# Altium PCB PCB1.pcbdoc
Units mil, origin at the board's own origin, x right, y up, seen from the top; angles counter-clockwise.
Board outline 2810 x 3710 mil, 2 copper layers (Top Layer, Bottom Layer), stack 62.2 mil thick; 16 components, 42 nets, 118 pads, 116 vias.
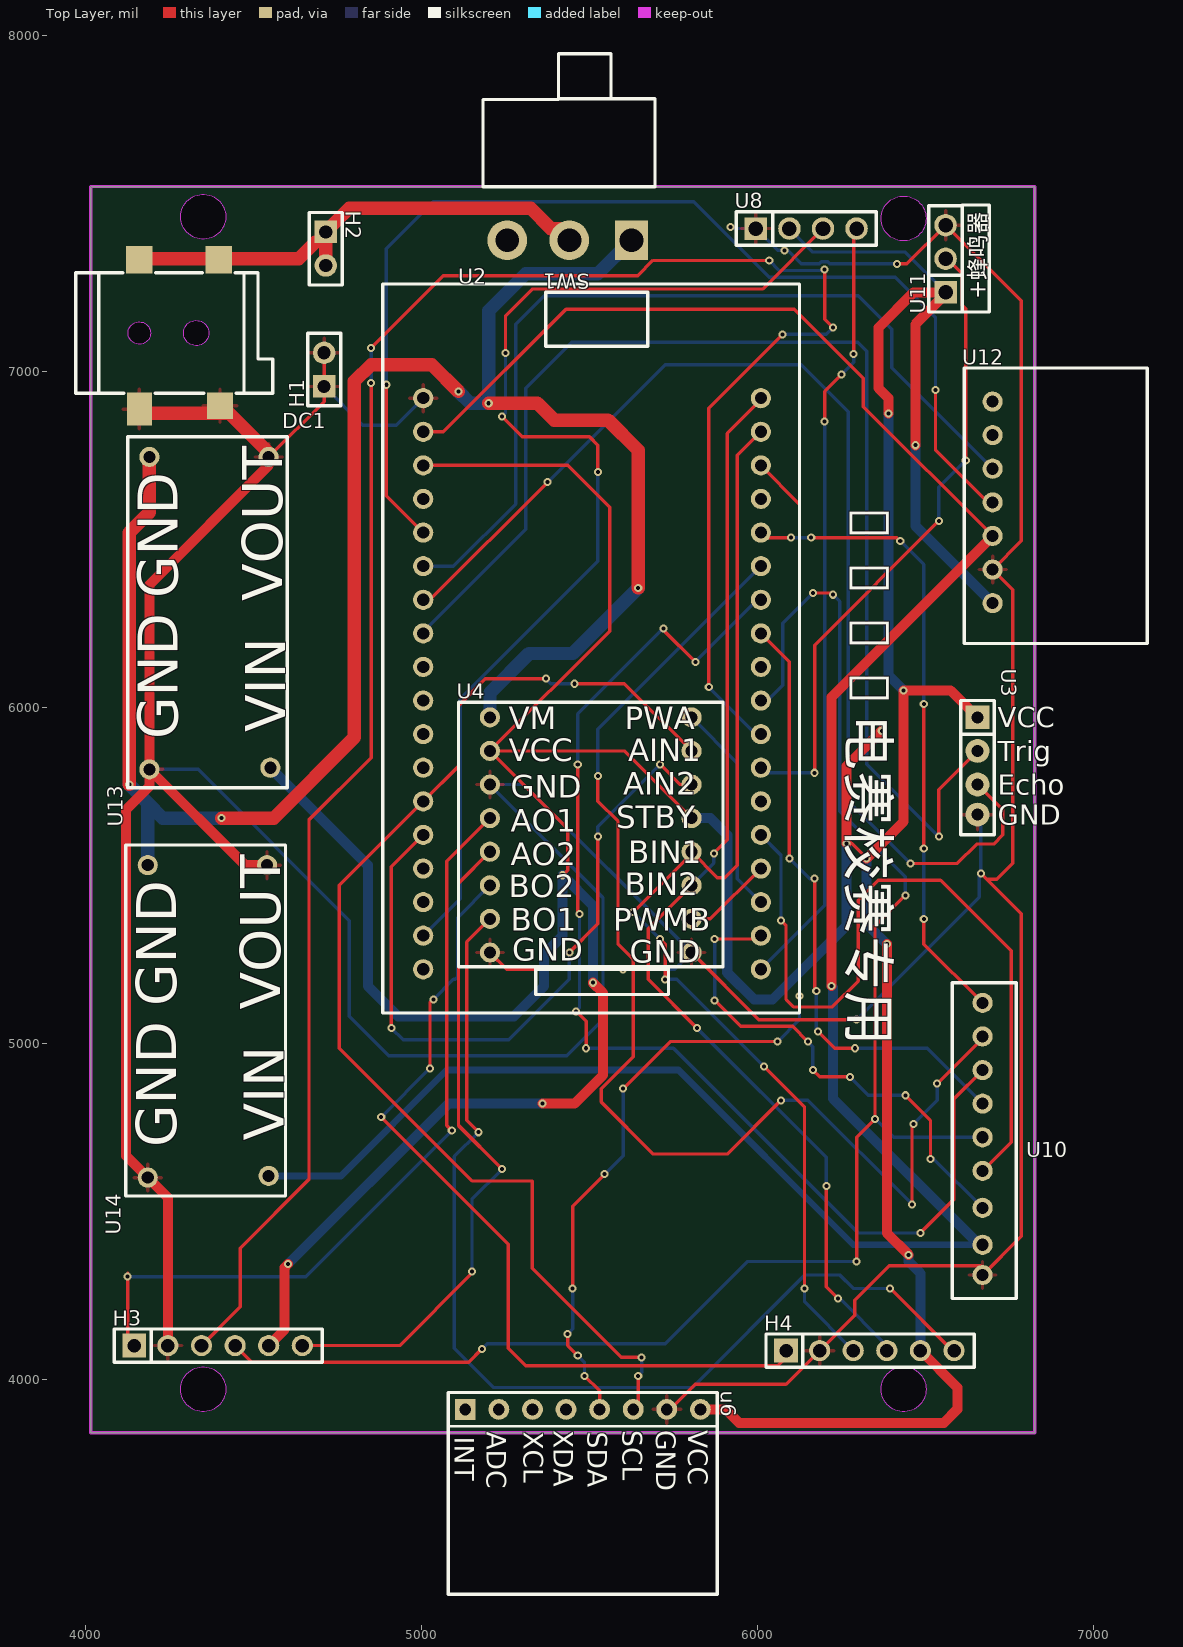
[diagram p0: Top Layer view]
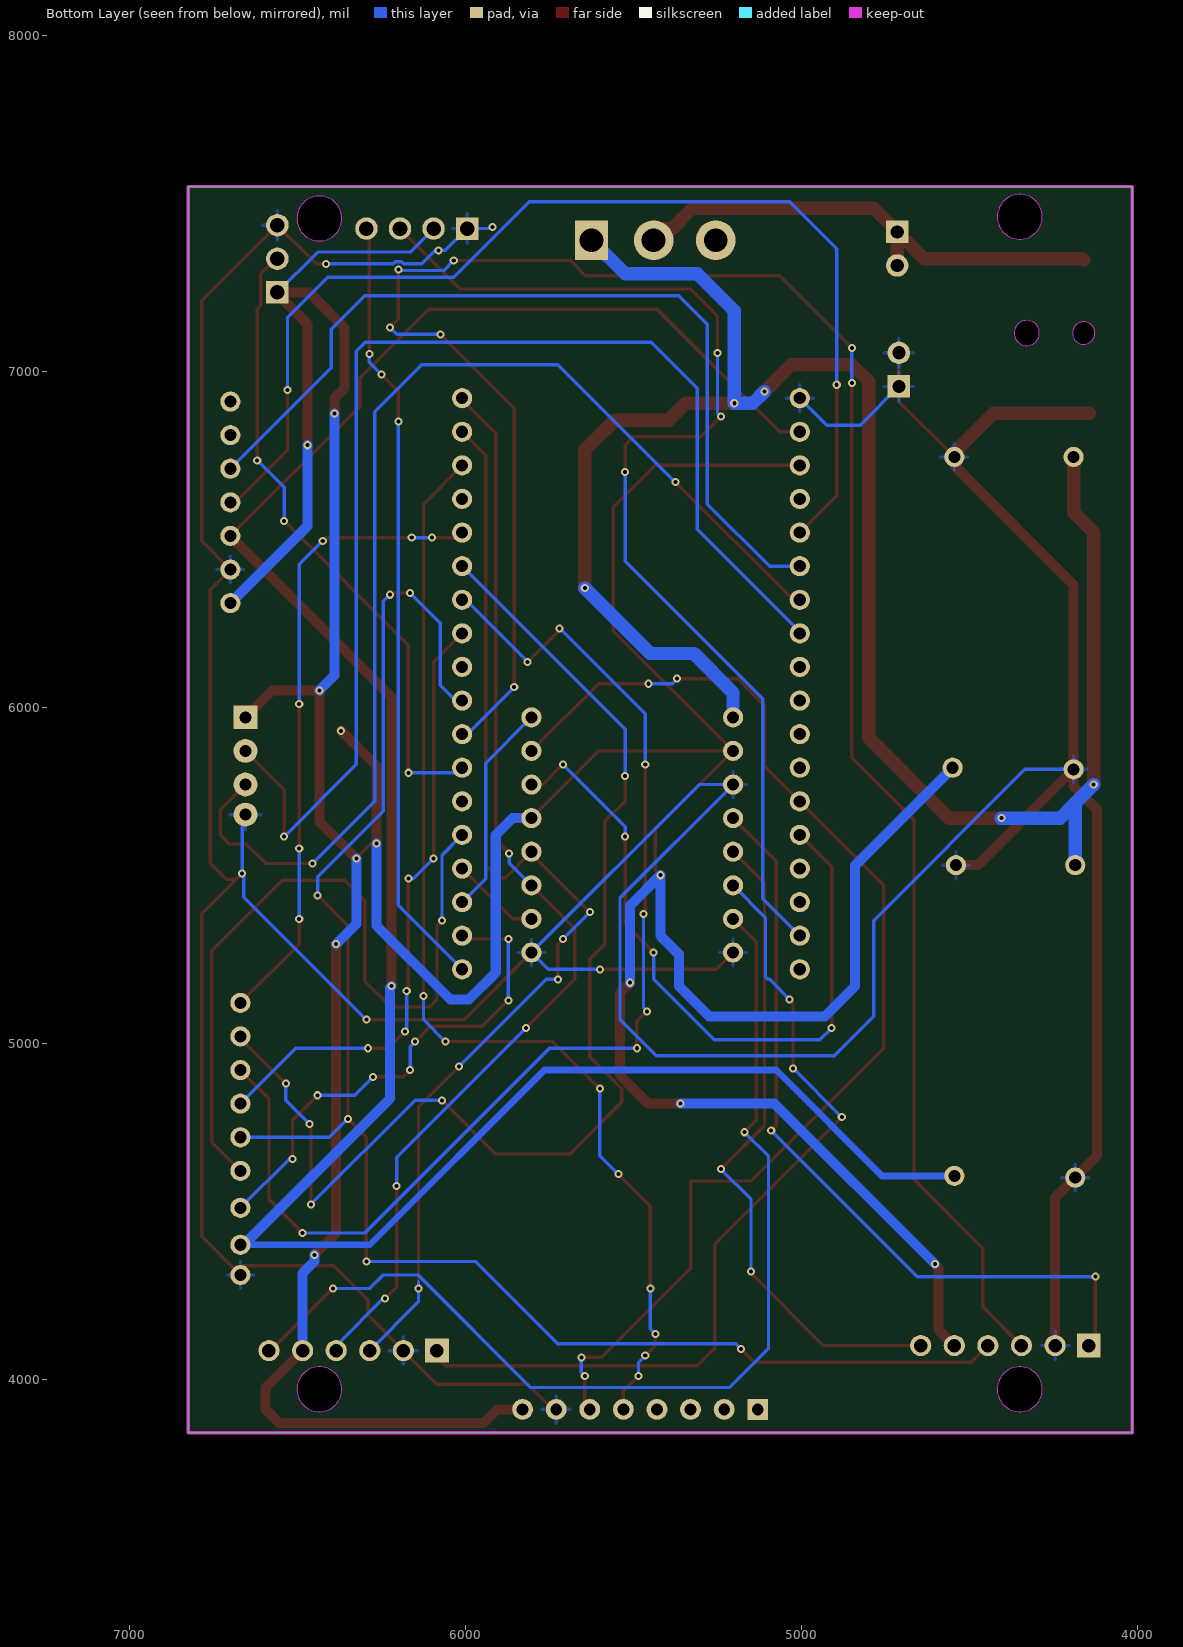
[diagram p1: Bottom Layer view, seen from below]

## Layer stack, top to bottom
Top Solder Mask Layer: solder mask 0.4, Dk 3.3
Top Layer: signal copper 1.4
Dielectric1: surface 59.4, FR4, Dk 4.5
Bottom Layer: signal copper 1.4
Bottom Solder Mask Layer: solder mask 0.4, Dk 3.3

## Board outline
4015,7550 4015,3840 6825,3840 6825,7550
cut-out: 4416.9,3970 4416.5,3962.8 4415.4,3955.6 4413.4,3948.6 4410.7,3941.9 4407.3,3935.5 4403.3,3929.5 4398.6,3924 4393.3,3919 4387.6,3914.6 4381.4,3910.9 4374.8,3907.8 4367.9,3905.5 4360.8,3904 4353.6,3903.2 4346.4,3903.2 4339.2,3904 4332.1,3905.5 4325.2,3907.8 4318.6,3910.9 4312.4,3914.6 4306.7,3919 4301.4,3924 4296.7,3929.5 4292.7,3935.5 4289.3,3941.9 4286.6,3948.6 4284.6,3955.6 4283.5,3962.8 4283.1,3970 4283.5,3977.2 4284.6,3984.4 4286.6,3991.4 4289.3,3998.1 4292.7,4004.5 4296.7,4010.5 4301.4,4016 4306.7,4021 4312.4,4025.4 4318.6,4029.1 4325.2,4032.2 4332.1,4034.5 4339.2,4036 4346.4,4036.8 4353.6,4036.8 4360.8,4036 4367.9,4034.5 4374.8,4032.2 4381.4,4029.1 4387.6,4025.4 4393.3,4021 4398.6,4016 4403.3,4010.5 4407.3,4004.5 4410.7,3998.1 4413.4,3991.4 4415.4,3984.4 4416.5,3977.2
cut-out: 6501.9,3970 6501.5,3962.8 6500.4,3955.6 6498.4,3948.6 6495.7,3941.9 6492.3,3935.5 6488.3,3929.5 6483.6,3924 6478.3,3919 6472.6,3914.6 6466.4,3910.9 6459.8,3907.8 6452.9,3905.5 6445.8,3904 6438.6,3903.2 6431.4,3903.2 6424.2,3904 6417.1,3905.5 6410.2,3907.8 6403.6,3910.9 6397.4,3914.6 6391.7,3919 6386.4,3924 6381.7,3929.5 6377.7,3935.5 6374.3,3941.9 6371.6,3948.6 6369.6,3955.6 6368.5,3962.8 6368.1,3970 6368.5,3977.2 6369.6,3984.4 6371.6,3991.4 6374.3,3998.1 6377.7,4004.5 6381.7,4010.5 6386.4,4016 6391.7,4021 6397.4,4025.4 6403.6,4029.1 6410.2,4032.2 6417.1,4034.5 6424.2,4036 6431.4,4036.8 6438.6,4036.8 6445.8,4036 6452.9,4034.5 6459.8,4032.2 6466.4,4029.1 6472.6,4025.4 6478.3,4021 6483.6,4016 6488.3,4010.5 6492.3,4004.5 6495.7,3998.1 6498.4,3991.4 6500.4,3984.4 6501.5,3977.2
cut-out: 4416.9,7460 4416.5,7452.8 4415.4,7445.6 4413.4,7438.6 4410.7,7431.9 4407.3,7425.5 4403.3,7419.5 4398.6,7414 4393.3,7409 4387.6,7404.6 4381.4,7400.9 4374.8,7397.8 4367.9,7395.5 4360.8,7394 4353.6,7393.2 4346.4,7393.2 4339.2,7394 4332.1,7395.5 4325.2,7397.8 4318.6,7400.9 4312.4,7404.6 4306.7,7409 4301.4,7414 4296.7,7419.5 4292.7,7425.5 4289.3,7431.9 4286.6,7438.6 4284.6,7445.6 4283.5,7452.8 4283.1,7460 4283.5,7467.2 4284.6,7474.4 4286.6,7481.4 4289.3,7488.1 4292.7,7494.5 4296.7,7500.5 4301.4,7506 4306.7,7511 4312.4,7515.4 4318.6,7519.1 4325.2,7522.2 4332.1,7524.5 4339.2,7526 4346.4,7526.8 4353.6,7526.8 4360.8,7526 4367.9,7524.5 4374.8,7522.2 4381.4,7519.1 4387.6,7515.4 4393.3,7511 4398.6,7506 4403.3,7500.5 4407.3,7494.5 4410.7,7488.1 4413.4,7481.4 4415.4,7474.4 4416.5,7467.2
cut-out: 6501.9,7455 6501.5,7447.8 6500.4,7440.6 6498.4,7433.6 6495.7,7426.9 6492.3,7420.5 6488.3,7414.5 6483.6,7409 6478.3,7404 6472.6,7399.6 6466.4,7395.9 6459.8,7392.8 6452.9,7390.5 6445.8,7389 6438.6,7388.2 6431.4,7388.2 6424.2,7389 6417.1,7390.5 6410.2,7392.8 6403.6,7395.9 6397.4,7399.6 6391.7,7404 6386.4,7409 6381.7,7414.5 6377.7,7420.5 6374.3,7426.9 6371.6,7433.6 6369.6,7440.6 6368.5,7447.8 6368.1,7455 6368.5,7462.2 6369.6,7469.4 6371.6,7476.4 6374.3,7483.1 6377.7,7489.5 6381.7,7495.5 6386.4,7501 6391.7,7506 6397.4,7510.4 6403.6,7514.1 6410.2,7517.2 6417.1,7519.5 6424.2,7521 6431.4,7521.8 6438.6,7521.8 6445.8,7521 6452.9,7519.5 6459.8,7517.2 6466.4,7514.1 6472.6,7510.4 6478.3,7506 6483.6,7501 6488.3,7495.5 6492.3,7489.5 6495.7,7483.1 6498.4,7476.4 6500.4,7469.4 6501.5,7462.2

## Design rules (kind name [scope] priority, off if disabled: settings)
BoardOutlineClearance copperThickness1oz [All] p0: genericclearance=10 ignorepadtopadclearanceinfootprint=FALSE except(0: Arc-SplitContinuation Track-SplitContinuation SMDPad-SplitContinuation THPad-SplitContinuation Via-SplitContinuation Fill-SplitContinuation Poly-SplitContinuation Region-SplitContinuation Text-SplitContinuation)
BoardOutlineClearance copperThickness2oz [All] p0: genericclearance=10 ignorepadtopadclearanceinfootprint=FALSE except(0: Arc-SplitContinuation Track-SplitContinuation SMDPad-SplitContinuation THPad-SplitContinuation Via-SplitContinuation Fill-SplitContinuation Poly-SplitContinuation Region-SplitContinuation Text-SplitContinuation)
BoardOutlineClearance Plane_innerPlane [All] p0: genericclearance=10 ignorepadtopadclearanceinfootprint=FALSE except(0: Arc-SplitContinuation Track-SplitContinuation SMDPad-SplitContinuation THPad-SplitContinuation Via-SplitContinuation Fill-SplitContinuation Poly-SplitContinuation Region-SplitContinuation Text-SplitContinuation)
BoardOutlineClearance Copper_copperRegion [All] p0: genericclearance=10 ignorepadtopadclearanceinfootprint=FALSE except(0: Arc-SplitContinuation Track-SplitContinuation SMDPad-SplitContinuation THPad-SplitContinuation Via-SplitContinuation Fill-SplitContinuation Poly-SplitContinuation Region-SplitContinuation Text-SplitContinuation)
BoardOutlineClearance otherClearance [All] p0: genericclearance=10 ignorepadtopadclearanceinfootprint=FALSE except(0: Arc-SplitContinuation Track-SplitContinuation SMDPad-SplitContinuation THPad-SplitContinuation Via-SplitContinuation Fill-SplitContinuation Poly-SplitContinuation Region-SplitContinuation Text-SplitContinuation)
Clearance copperThickness1oz [All] p1: gap=7 ignorepadtopadclearanceinfootprint=FALSE
Clearance copperThickness2oz [All] p1: gap=7 ignorepadtopadclearanceinfootprint=FALSE
Clearance Plane_innerPlane [All] p1: gap=7 ignorepadtopadclearanceinfootprint=FALSE
Clearance Copper_copperRegion [All] p1: gap=7 ignorepadtopadclearanceinfootprint=FALSE
Clearance otherClearance [All] p1: gap=7 ignorepadtopadclearanceinfootprint=FALSE
DiffPairsRouting differentialPair [All] p1: maxuncoupledlength=10 minlimit=6 maxlimit=Infinity mostfreqgap=6 toplayer_minwidth=5 toplayer_prefwidth=10 toplayer_maxwidth=100 bottomlayer_minwidth=5 bottomlayer_prefwidth=10 bottomlayer_maxwidth=100
PasteMaskExpansion pasteMaskExpansion [All] p1: expansion=0
PlaneConnect innerPlane [All] p1: planeconnectstyle=Relief reliefexpansion=20 reliefentries=4 reliefconductorwidth=10 reliefairgap=10
PolygonConnect copperRegion [All] p1: connectstyle=Relief reliefentries=4 reliefconductorwidth=10 polygonreliefangle="90 Angle" airgapwidth=10
RoutingVias viaSize [All] p1: viastyle="Through Hole" holewidth=12.0078 minholewidth=11.811 maxholewidth=248.0314 width=12.0078 minwidth=11.811 maxwidth=248.0314
SolderMaskExpansion solderMaskExpansion [IsVia] p1: useseparateexpansions=TRUE expansion=-1000 expansionbottom=-1000
SolderMaskExpansion solderMaskExpansion [All] p2: useseparateexpansions=TRUE expansion=2 expansionbottom=2
Width copperThickness1oz [All] p1: maxlimit=100 minlimit=5 preferedwidth=10
Width copperThickness2oz [All] p1: maxlimit=100 minlimit=8 preferedwidth=10

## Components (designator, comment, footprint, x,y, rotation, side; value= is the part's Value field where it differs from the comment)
DC1 "DC050-T" DC-IN_DC050-T 4280,7110 r0 top
H1 "" HDR-TH_2P-P2.54-V-F 4710,7005 r90 top
H2 "" HDR-TH_2P-P2.54-V-F 4715,7365 r270 top
H3 "" HDR-TH_6P-P2.54-V-F 4395,4100 r0 top
H4 "" HDR-TH_6P-P2.54-V-F 6335,4085 r0 top
SW1 "SS-12D06L5" SW-TH_3P-P4.70_L11.1-W12.7 5440,7390 r180 top
U2 "" 5307 5265,7150 r0 top
U3 "HC-SR04" HC-SR04 6655,5820 r270 top
U4 "" TB6612 5110,6015 r0 top
u6 "mpu6050" MPU6050模块 5480,3960 r270 top
U8 "OLED-4P" HDR-TH_4P-P2.54-V-F 6145,7425 r0 top
U10 "" huidu 6650,4630 r0 top
U11 "蜂鸣器" 蜂鸣器 6560,7335 r90 top
U12 "" tcs34725 6885,6540 r0 top
U13 "" MP2236 4130,5750 r90 top
U14 "" MP2236 4125,4535 r90 top

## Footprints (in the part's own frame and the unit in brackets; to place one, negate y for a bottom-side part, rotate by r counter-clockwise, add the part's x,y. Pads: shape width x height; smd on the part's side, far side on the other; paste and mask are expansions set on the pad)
5307 [mil]
  round 60 hole 36: 1(745,-230) 2(745,-330) 3(745,-430) 4(745,-530) 5(745,-630) 6(745,-730) 7(745,-830) 8(745,-930) 9(745,-1030) 10(745,-1130) 11(745,-1230) 12(745,-1330) 13(745,-1430) 14(745,-1530) 15(745,-1630) 16(745,-1730) 17(745,-1830) 18(745,-1930) 19(-260,-1930) 20(-260,-1830) 21(-260,-1730) 22(-260,-1630) 23(-260,-1530) 24(-260,-1430) 25(-260,-1330) 26(-260,-1230) 27(-260,-1130) 28(-260,-1030) 29(-260,-930) 30(-260,-830) 31(-260,-730) 32(-260,-630) 33(-260,-530) 34(-260,-430) 35(-260,-330) 36(-260,-230)
  silkscreen extent -380,-2060 860,110
DC-IN_DC050-T [mil]
  rect 78.7x82.7 smd paste+0 mask+2: 1(-120.1,222.4) 1(116.1,222.4)
  rect 74.8x98.4 smd paste+0 mask+2: 2(-120.1,-222.4)
  rect 78.7x78.7 smd paste+0 mask+2: 3(120.1,-212.6)
  Board Outline Layer lines w0.1: -153.4,1.4 -152.7,-3.7 -151.1,-8.6 -148.8,-13.2 -145.9,-17.4 -142.3,-21 -138.3,-24.2 -133.8,-26.6 -128.9,-28.3 -123.9,-29.3 -118.8,-29.5 -113.7,-28.9 -108.8,-27.6 -104.1,-25.5 -99.8,-22.7 -96,-19.3 -92.7,-15.3 -90.1,-10.9 -88.2,-6.2 -87,-1.2 -86.6,3.9 -87,9 -88.2,14 -90.1,18.8 -92.7,23.2 -96,27.1 -99.8,30.6 -104.1,33.3 -108.8,35.4 -113.7,36.8 -118.8,37.4 -123.9,37.2 -128.9,36.2 -133.8,34.5 -138.3,32 -142.3,28.9 -145.9,25.2 -148.8,21 -151.1,16.4 -152.7,11.6 -153.4,6.5 -153.4,1.4 ; 11.9,1.2 12.7,-4.2 14.3,-9.4 16.6,-14.4 19.6,-18.9 23.3,-23 27.4,-26.5 32.1,-29.3 37.1,-31.5 42.4,-32.8 47.8,-33.4 53.3,-33.2 58.7,-32.2 63.8,-30.5 68.7,-28 73.1,-24.8 77.1,-21 80.4,-16.7 83.1,-11.9 85,-6.8 86.2,-1.5 86.6,3.9 86.2,9.4 85,14.7 83.1,19.8 80.4,24.6 77.1,28.9 73.1,32.7 68.7,35.9 63.8,38.4 58.7,40.1 53.3,41.1 47.8,41.3 42.4,40.7 37.1,39.3 32.1,37.2 27.4,34.4 23.3,30.9 19.6,26.8 16.6,22.2 14.3,17.3 12.7,12.1 11.9,6.7 11.9,1.2
  Board Outline Layer region: -86.6,3.9 -87,-1.2 -88.2,-6.2 -90.1,-10.9 -92.7,-15.3 -96,-19.3 -99.8,-22.7 -104.1,-25.5 -108.8,-27.6 -113.7,-28.9 -118.8,-29.5 -123.9,-29.3 -128.9,-28.3 -133.8,-26.6 -138.3,-24.2 -142.3,-21 -145.9,-17.4 -148.8,-13.2 -151.1,-8.6 -152.7,-3.7 -153.4,1.4 -153.4,6.5 -152.7,11.6 -151.1,16.4 -148.8,21 -145.9,25.2 -142.3,28.9 -138.3,32 -133.8,34.5 -128.9,36.2 -123.9,37.2 -118.8,37.4 -113.7,36.8 -108.8,35.4 -104.1,33.3 -99.8,30.6 -96,27.1 -92.7,23.2 -90.1,18.8 -88.2,14 -87,9
  Board Outline Layer region: -86.6,3.9 -87,-1.2 -88.2,-6.2 -90.1,-10.9 -92.7,-15.3 -96,-19.3 -99.8,-22.7 -104.1,-25.5 -108.8,-27.6 -113.7,-28.9 -118.8,-29.5 -123.9,-29.3 -128.9,-28.3 -133.8,-26.6 -138.3,-24.2 -142.3,-21 -145.9,-17.4 -148.8,-13.2 -151.1,-8.6 -152.7,-3.7 -153.4,1.4 -153.4,6.5 -152.7,11.6 -151.1,16.4 -148.8,21 -145.9,25.2 -142.3,28.9 -138.3,32 -133.8,34.5 -128.9,36.2 -123.9,37.2 -118.8,37.4 -113.7,36.8 -108.8,35.4 -104.1,33.3 -99.8,30.6 -96,27.1 -92.7,23.2 -90.1,18.8 -88.2,14 -87,9
  Board Outline Layer region: 86.6,3.9 86.2,-1.5 85,-6.8 83.1,-11.9 80.4,-16.7 77.1,-21 73.1,-24.8 68.7,-28 63.8,-30.5 58.7,-32.2 53.3,-33.2 47.8,-33.4 42.4,-32.8 37.1,-31.5 32.1,-29.3 27.4,-26.5 23.3,-23 19.6,-18.9 16.6,-14.4 14.3,-9.4 12.7,-4.2 11.9,1.2 11.9,6.7 12.7,12.1 14.3,17.3 16.6,22.2 19.6,26.8 23.3,30.9 27.4,34.4 32.1,37.2 37.1,39.3 42.4,40.7 47.8,41.3 53.3,41.1 58.7,40.1 63.8,38.4 68.7,35.9 73.1,32.7 77.1,28.9 80.4,24.6 83.1,19.8 85,14.7 86.2,9.4
  Board Outline Layer region: 86.6,3.9 86.2,-1.5 85,-6.8 83.1,-11.9 80.4,-16.7 77.1,-21 73.1,-24.8 68.7,-28 63.8,-30.5 58.7,-32.2 53.3,-33.2 47.8,-33.4 42.4,-32.8 37.1,-31.5 32.1,-29.3 27.4,-26.5 23.3,-23 19.6,-18.9 16.6,-14.4 14.3,-9.4 12.7,-4.2 11.9,1.2 11.9,6.7 12.7,12.1 14.3,17.3 16.6,22.2 19.6,26.8 23.3,30.9 27.4,34.4 32.1,37.2 37.1,39.3 42.4,40.7 47.8,41.3 53.3,41.1 58.7,40.1 63.8,38.4 68.7,35.9 73.1,32.7 77.1,28.9 80.4,24.6 83.1,19.8 85,14.7 86.2,9.4
  Multi-Layer board cut-out: -86.6,3.9 -87,-1.2 -88.2,-6.2 -90.1,-10.9 -92.7,-15.3 -96,-19.3 -99.8,-22.7 -104.1,-25.5 -108.8,-27.6 -113.7,-28.9 -118.8,-29.5 -123.9,-29.3 -128.9,-28.3 -133.8,-26.6 -138.3,-24.2 -142.3,-21 -145.9,-17.4 -148.8,-13.2 -151.1,-8.6 -152.7,-3.7 -153.4,1.4 -153.4,6.5 -152.7,11.6 -151.1,16.4 -148.8,21 -145.9,25.2 -142.3,28.9 -138.3,32 -133.8,34.5 -128.9,36.2 -123.9,37.2 -118.8,37.4 -113.7,36.8 -108.8,35.4 -104.1,33.3 -99.8,30.6 -96,27.1 -92.7,23.2 -90.1,18.8 -88.2,14 -87,9
  Multi-Layer board cut-out: 86.6,3.9 86.2,-1.5 85,-6.8 83.1,-11.9 80.4,-16.7 77.1,-21 73.1,-24.8 68.7,-28 63.8,-30.5 58.7,-32.2 53.3,-33.2 47.8,-33.4 42.4,-32.8 37.1,-31.5 32.1,-29.3 27.4,-26.5 23.3,-23 19.6,-18.9 16.6,-14.4 14.3,-9.4 12.7,-4.2 11.9,1.2 11.9,6.7 12.7,12.1 14.3,17.3 16.6,22.2 19.6,26.8 23.3,30.9 27.4,34.4 32.1,37.2 37.1,39.3 42.4,40.7 47.8,41.3 53.3,41.1 58.7,40.1 63.8,38.4 68.7,35.9 73.1,32.7 77.1,28.9 80.4,24.6 83.1,19.8 85,14.7 86.2,9.4
  silkscreen extent -309,-175 278,183
HC-SR04 [mil]
  rect 70.9x70.9 hole 36: 1(-150,0)
  round 70.9 hole 36: 2(-50,0) 3(50,0) 4(139.5,0)
  silkscreen extent -200,-50 200,50
HDR-TH_2P-P2.54-V-F [mil]
  rect 66.9x66.9 hole 39.4: 1(-50,0)
  round 66.9 hole 39.4: 2(50,0)
  silkscreen extent -108,-49 108,49
HDR-TH_4P-P2.54-V-F [mil]
  rect 66.9x66.9 hole 43.3: 1(-150,0)
  round 66.9 hole 43.3: 2(-50,0) 3(50,0) 4(150,0)
  silkscreen extent -208,-50 208,50
HDR-TH_6P-P2.54-V-F [mil]
  rect 70.9x70.9 hole 40.2: 1(-250,0)
  round 63 hole 40.2: 2(-150,0) 3(-50,0) 4(50,0) 5(150,0) 6(250,0)
  silkscreen extent -310,-49 310,49
huidu [mil]
  round 60 hole 36: 1(20,490) 2(20,390) 3(20,290) 4(20,190) 5(20,90) 6(20,-10) 7(20,-120) 8(20,-230) 9(20,-320)
  silkscreen extent -70,-390 120,550
MP2236 [mil]
  round 60 hole 36: 1(65,-60) 2(995,-60) 3(995,-415) 4(70,-420)
  silkscreen extent 10,-470 1055,5
MPU6050模块 [mil]
  round 62 hole 35: ADC(50,-249.9) GND(50,250.1) SCL(50,150.1) SDA(50,50.1) VCC(50,350.1) XCL(50,-149.9) XDA(50,-49.9)
  rect 62x62 hole 35: INT(50,-349.9)
  silkscreen extent 0,-400 600,400
SW-TH_3P-P4.70_L11.1-W12.7 [mil]
  rect 98.4x118.1 hole 70.9: 1(-185,0)
  round 118.1 hole 70.9: 2(0,0) 3(185,0)
  silkscreen extent -255,-555 257,-159
TB6612 [mil]
  round 60 hole 36: 1(93.7,-45) 2(93.7,-145) 3(93.7,-245) 4(93.7,-345) 5(93.7,-445) 6(93.7,-545) 7(93.7,-645) 8(93.7,-745) 9(693.7,-745) 10(693.7,-645) 11(693.7,-545) 12(693.7,-445) 13(693.7,-345) 14(693.7,-245) 15(693.7,-145) 16(693.7,-45)
  silkscreen extent 0,-787 787,0
tcs34725 [mil]
  round 60 hole 36: 1(-185,370) 2(-185,270) 3(-185,170) 4(-185,70) 5(-185,-30) 6(-185,-130) 7(-185,-230)
  silkscreen extent -270,-350 275,470
蜂鸣器 [mil]
  rect 66.9x66.9 hole 43.3 paste+0 mask+2: 1(-100,0)
  round 66.9 hole 43.3 paste+0 mask+2: 2(0,0) 3(100,0)
  silkscreen extent -158,-130 160,50

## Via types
v1: diameter 24, hole 12, Top Layer to Bottom Layer, 116 vias

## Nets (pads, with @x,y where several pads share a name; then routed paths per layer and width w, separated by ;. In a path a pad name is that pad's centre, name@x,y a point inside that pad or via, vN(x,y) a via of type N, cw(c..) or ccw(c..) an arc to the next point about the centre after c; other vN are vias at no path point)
+3.3V: U2.35 U10.8 U12.5 U14.4 | length 7137.5
  Top Layer w10: U2.35 5065,6820 5430,7185 6110,7185 6315,6980 6315,6895 U12.5
  Top Layer w30: v1(6220,5170) 6220,6030 U12.5
  Bottom Layer w20: U14.4 4760,4605 5075,4920 5765,4920 6285,4400 U10.8@6660,4400
  Bottom Layer w30: v1(6220,5170) 6225,5165 6225,4835 6660,4400 U10.8
+5V: H3.5 H4.5 U2.34 U3.1 U4.2 U4.13 u6.VCC U8.2 U11.1 U12.7 U13.4 | length 14469.1
  Top Layer w10: U2.34 5435,6720 5560,6595 5560,6226.3 U4.2 ; v1(5420,5500) 5435,5515 5435,5638.7 U4.2 ; U4.13 5603.7,5870 U4.2 ; v1(6265,5595) 6280,5595 v1(6325,5550)
  Top Layer w30: H3.5 4592.5,4147.5 4592.5,4332.5 v1(4602.5,4342.5) ; v1(5360,4820.1) 5455.1,4820.1 5540,4905 5540,5150 v1(5510,5180) ; u6.VCC 5905,3910 5945,3870 6555,3870 6595,3910 6595,3975 H4.5 ; v1(6265,5595) 6265,5825 v1(6370,5930) ; v1(6325,5550) 6435,5660 v1(6435,6050) 6575,6050 U3.1 ; v1(6385,5295) 6385,4435 v1(6450,4370) ; v1(6390,6875) 6390,6920 6360,6950 6360,7130 6465,7235 6565,7235 6470,7140 v1(6470,6780)
  Bottom Layer w10: U8.2 6165,7355 6440,7355 U11.1
  Bottom Layer w30: U13.4 4840,5530 4840,5170 4930,5080 5275,5080 5365,5170 5365,5265 5420,5320 v1(5420,5500) 5510,5410 v1(5510,5180) ; v1(4602.5,4342.5) 5080.1,4820.1 v1(5360,4820.1) ; U4.13 5860,5670 5910,5620 5910,5210 5990,5130 6045,5130 6265,5350 v1(6265,5595) ; v1(6325,5550) 6325,5355 v1(6385,5295) ; v1(6390,6875) 6390,6095 v1(6435,6050) ; v1@6450,4371 6450,4350 6485,4315 H4.5 ; v1(6470,6780) 6470,6540 U12.7
+12V: SW1.1 U4.1 U13.2 U14.2 | length 5903
  Top Layer w40: v1(4130,5770) 4130,6520 4190,6580 U13.2 ; v1(4405,5670) 4560,5670 4800,5910 4800,6970 4850,7020 5030,7020 v1(5110,6940) ; v1(5200,6905) 5345,6905 5395,6855 5555,6855 5645,6765 v1(5645,6355)
  Bottom Layer w10: SW1.1 SW1.1@5625,7425
  Bottom Layer w40: v1(4130,5770) 4185,5715 ; U14.2 4185,5715 ; v1(4405,5670) 4230,5670 4185,5715 ; v1(5110,6940) 5145,6905 v1(5200,6905) 5200,7180 5310,7290 5525,7290 SW1.1 ; U4.1 5203.7,6043.7 5320,6160 5450,6160 v1(5645,6355)
AO1: H3.6 U4.5 | length 1979
  Top Layer w10: H3.6 4935,4100 5150,4315 v1(5150,4320) ; U4.5 5110,5476.3 5110,4755 v1(5240,4625)
  Bottom Layer w10: v1(5150,4320) 5150,4535 v1(5240,4625)
AO2: H3.1 U4.4 | length 2358
  Top Layer w10: v1@4125,4315 v1(4125,4305) 4125,4120 H3.1 ; v1(5090,4740) 5075,4755 5075,5541.3 U4.4
  Bottom Layer w10: v1(4125,4305) 4655,4305 v1(5090,4740)
BO1: H4.6 U4.7 | length 3135.4
  Top Layer w10: v1(5170,4735) 5135,4770 5135,5301.3 U4.7 ; v1(6395,4270) 6585,4080 H4.6@6585,4065
  Bottom Layer w10: v1(5170,4735) 5097.9,4662.9 5097.9,4092.1 5215,3975 5805.2,3975 6140.2,4310 6245,4310 6285,4270 v1(6395,4270)
BO2: H4.1 U4.6 | length 2530.5
  Top Layer w10: v1(4880,4780) 5257.9,4402.1 5257.9,4092.1 5310,4040 6060,4040 H4.1@6085,4065 ; v1(5025,4925) 5025,5120 v1(5035,5130)
  Bottom Layer w10: v1(4880,4780) v1(5025,4925) ; v1(5035,5130) 5095,5190 5100,5190 5107.1,5197.1 5107.1,5373.4 U4.6
GND: DC1.2 DC1.3 H1.1 H1.2 H3.2 H4.2 U2.36 U3.4 U4.3 U4.8 U4.9 u6.GND U8.1 U10.9 U11.3 U12.6 U13.1 U13.3 U14.1 U14.3 | length 15452.9
  Top Layer w10: U13.3 4710,6910 H1.1 H1.2 ; U4.8 5253.7,5220 v1(5600,5220) ; u6.GND 5740,3910 5815,3985 6085,3985 H4.2 6290,4190 6290,4235 6392.1,4337.1 6662.9,4337.1 U10.9@6670,4330 ; U4.9 6003.7,5070 v1(6295,5070) ; v1(6415,7320) 6445,7320 U11.3 6785,7210 6785,6495 U12.6 6760,6350 6760,5535 6712.9,5487.9 6682.6,5487.9 ; v1(6665,5505.5) 6682.6,5487.9 ; U10.9 6785,4425 6785,5385.5 6682.6,5487.9
  Top Layer w30: H3.2 4245,4540 U14.1 ; U14.3 4475,5530 U13.1 ; U13.3 4545,6720 4190,6365 U13.1 ; U14.1@4170,4615 4185,4610 U14.1 ; U14.1@4170,4615 4120,4665 4120,5695 4190,5765 U13.1 ; U14.1@4170,4615 U14.1
  Top Layer w40: DC1.2@4143.4,6875 4427.5,6875 4545,6757.5 U13.3
  Bottom Layer w10: U13.1 4335,5815 4785,5365 4785,5080 4902.1,4962.9 5432.9,4962.9 5540,5070 5540,5433.7 U4.3 5303.7,5770 U4.9 5753.7,5220 v1(5600,5220) ; H1.1 4825,6840 4925,6840 U2.36 ; v1(5920,7430) 5925,7425 U8.1 6060,7360 v1(6080,7360) 6090,7360 6130,7320 6184.5,7320 6190.5,7326 6209.5,7326 6215.5,7320 v1(6415,7320) ; v1(6295,5070) 6660,5435 v1@6660,5510.5 ; U3.4 6665,5670.5 v1@6665,5510.5
NRST: U2.33
PA0: U2.32 U12.4 | length 3355.7
  Top Layer w10: v1(4895,6960) 4895,6630 U2.32 ; v1(6530,6945) 6530,6765 6685,6610 U12.4
  Bottom Layer w10: v1(4895,6960) 4895,7365 5035,7505 5810,7505 6035,7280 6410,7280 6530,7160 v1(6530,6945)
PA1: U2.31 U12.3 | length 2622.5
  Bottom Layer w10: U2.31 5095,6420 5280,6605 5280,7140 5365,7225 6300,7225 6400,7125 6400,7010 U12.3
PA2: U2.30 U3.3 | length 3525.8
  Top Layer w10: U2.30 5025,6320 v1(5375,6670) ; v1(6455,5535) 6595,5535 6652.9,5592.9 6702.9,5592.9 6730,5620 6730,5695 U3.3
  Bottom Layer w10: v1(5375,6670) 5725,7020 6130,7020 6270,6880 6270,5720 v1(6455,5535)
PA3: U2.29 U3.2 | length 3778
  Top Layer w10: v1(6540,5615) 6540,5755 U3.2
  Bottom Layer w10: U2.29@5000,6220 5310,6530 5310,6950 5447,7087 6298,7087 6325,7060 6325,5830 v1(6540,5615)
PA4: U2.28
PA5: U2.27
PA6: U2.26
PA7: U2.25
PA8: U2.24 U4.15 u6.SCL | length 3581.6
  Top Layer w10: v1(5370,6085) 5190,6085 5110,6005 5110,5825 U2.24 4755,5470 4755,4985 5150,4590 5329.9,4590 5329.9,4330.1 5595,4065 v1(5655,4065) ; v1(5455,6070) 5603.7,6070 U4.15 ; u6.SCL 5645,3924.9 v1(5645,4010)
  Bottom Layer w10: v1(5370,6085) 5385,6070 v1(5455,6070) ; v1(5645,4010) 5655,4020 v1(5655,4065)
PA9: U2.23 U4.14 | length 2103.8
  Top Layer w10: v1(4910,5045) 4910,5525 U2.23 ; v1(5440,5270) 5525,5355 v1(5525,5615) ; v1(5710,5830) 5770,5770 U4.14
  Bottom Layer w10: v1(4910,5045) 4945,5010 5260,5010 5440,5190 v1(5440,5270) ; v1(5525,5615) 5525,5645 v1(5710,5830)
PA10: U2.22
PA11: U2.21
PA12: U2.20 U8.3 | length 3352.4
  Top Layer w10: v1(5240,6865) 5300,6805 5500,6805 5525,6780 v1(5525,6700) ; v1(5250,7055) 5250,7165 5330,7245 6015,7245 U8.3
  Bottom Layer w10: U2.20 5115,5430 5115,6025 5525,6435 v1(5525,6700) ; v1(5240,6865) 5240,6867.1 5250,6877.1 v1(5250,7055)
PA13: U2.19
PA14: U2.18 U8.4 | length 2323.1
  Top Layer w10: v1(6200,6850) 6200,6940 v1(6250,6990) ; v1(6286.3,7051.3) 6286.3,7416.3 U8.4
  Bottom Layer w10: U2.18 6200,5410 v1(6200,6850) ; v1(6250,6990) 6286.3,7026.3 v1(6286.3,7051.3)
PA15: U2.17 U10.7 | length 1485.8
  Top Layer w10: v1(5872.5,5127.5) 5950,5050 6105,5050 v1(6150,5005) ; v1(5872.5,5310) 6000,5310 U2.17 ; v1(6165,4920) 6185,4900 v1(6275,4900) ; v1(6440,4845) 6515,4770 v1(6515,4655)
  Bottom Layer w10: v1(5872.5,5127.5) v1(5872.5,5310) ; v1(6150,5005) 6165,4990 v1(6165,4920) ; v1(6275,4900) 6330,4845 v1(6440,4845) ; v1(6515,4655) 6525,4655 U10.7
PA16: U2.16 U4.16 | length 635.5
  Bottom Layer w10: U4.16 5940,5833.7 5940,5490 U2.16
PA17: U2.15 U4.10 | length 268.4
  Top Layer w10: U4.10 5860,5370 U2.15
PA18: U2.14 U10.6 | length 2274.2
  Top Layer w10: v1(6070,5365) 6085,5350 6085,5130 6107.1,5107.9 6222.9,5107.9 6300,5185 6300,5425 6360,5485 6545,5485 6755,5275 6755,4705 U10.6
  Bottom Layer w10: U2.14 6070,5560 v1(6070,5365)
PA19: U2.13
PA20: U2.12 U11.2 | length 1905.4
  Top Layer w10: v1(6170,5805) 6170,6185 v1(6540,6555) ; U11.2@6565,7335 6609.4,7290.6 6609.4,7197 6620,7186.4 v1(6620,6735)
  Bottom Layer w10: U2.12 6025,5805 v1(6170,5805) ; v1(6540,6555) 6540,6655 v1(6620,6735)
PA21: H3.3 U2.11 | length 6346.3
  Top Layer w10: H3.3 4460,4215 4460,4390 4665,4595 4665,5665 4850,5850 v1(4850,6965) ; v1(4850,7070) 5065,7285 5643.8,7285 5688.8,7330 v1(6035,7330) ; v1(5855,6060) 5855,6890 v1(6075,7110) ; v1(6200,7303) 6200,7155 v1(6225,7130)
  Bottom Layer w10: v1(4850,6965) v1(4850,7070) ; v1(5855,6060) 5995,5920 U2.11 ; v1(6035,7330) 6065,7300 6197,7300 v1(6200,7303) ; v1(6075,7110) 6205,7110 v1(6225,7130)
PA22: H3.4 U2.10 U10.5 | length 4931.6
  Top Layer w10: H3.4 4495,4050 5140,4050 v1(5180,4090) ; v1(6165,6340) 6220,6340 v1(6225,6335) ; v1(6295,4350) 6295,4720 v1(6350,4775) 6350,5350 v1(6440,5440)
  Bottom Layer w10: v1(5180,4090) 5195,4105 5725,4105 5970,4350 v1(6295,4350) ; U2.10 6012.1,6017.9 6027.9,6017.9 6075,6065 6075,6250 v1(6165,6340) ; v1(6225,6335) 6245,6315 6245,5690 6440,5495 v1(6440,5440) ; v1(6350,4775) 6405,4720 U10.5
PA23: U2.9
PA24: U2.8 U10.4 | length 1843.3
  Top Layer w10: U2.8 6095,6135 v1(6095,5550) ; v1(6170,5490) 6170,5160 v1(6175,5155) ; v1(6180,5035) 6230,4985 v1(6290,4985)
  Bottom Layer w10: v1(6095,5550) 6155,5490 v1(6170,5490) ; v1(6175,5155) 6175,5040 v1(6180,5035) ; v1(6290,4985) 6505,4985 U10.4
PA25: U2.7 U10.3 | length 3569.7
  Top Layer w10: v1(5460,5095) 5490,5065 v1(5490,4985) ; v1(5465,5830) 5465,5390 v1(5470,5385) ; v1(5720,6235) 5720,6230 v1(5815,6135) ; v1(6485,4435) 6585,4535 6585,4835 U10.3
  Bottom Layer w10: v1(5460,5095) 5470,5105 v1(5470,5385) ; v1(5465,5830) 5465,5980 v1(5720,6235) ; v1(5490,4985) 5750,4985 6300,4435 v1(6485,4435) ; v1(5815,6135) 6000,6320 U2.7
PA26: U2.6 U10.2 | length 3649.6
  Top Layer w10: v1(5525,5795) 5525,5720 5585,5660 5585,5295 5630,5250 5630,4960 5535,4865 5535,4825 5690,4670 5910,4670 v1(6070,4830) ; v1(6460,4520) 6460,4755 v1(6465,4760) ; v1(6535,4880) 6670,5015 U10.2
  Bottom Layer w10: v1(5525,5795) 5525,5935 U2.6 ; v1(6070,4830) 6150,4830 v1(6460,4520) ; v1(6465,4760) 6535,4830 v1(6535,4880)
PA27: U2.5 U10.1 | length 1901.8
  Top Layer w10: U2.5 6025,6505 v1(6100,6505) ; v1(6160,6505) 6415,6505 v1(6425,6495) ; v1(6495,5370) 6495,5295 U10.1 ; v1(6495,5580) v1(6495,6010)
  Bottom Layer w10: v1(6100,6505) v1(6160,6505) ; v1(6425,6495) 6495,6425 v1(6495,6010) ; v1(6495,5370) v1(6495,5580)
PB6: U2.4
PB7: U2.3 u6.SDA | length 3370.3
  Top Layer w10: v1(5435,4135) 5435,4100 v1(5465,4070) ; v1(5450,4270) 5450,4515 v1(5545,4610) ; v1(5485,4010) 5530.1,3964.9 u6.SDA ; v1(5600,4865) 5740,5005 v1(6060,5005) ; U2.3 6125,6605 v1(6125,5140)
  Bottom Layer w10: v1(5435,4135) 5450,4150 v1(5450,4270) ; v1(5465,4070) 5485,4050 v1(5485,4010) ; v1(5545,4610) 5600,4665 v1(5600,4865) ; v1(6060,5005) 6125,5070 v1(6125,5140)
PB8: H4.3 U2.2 U4.12 | length 3371
  Top Layer w10: v1(5630,5390) 5803.7,5563.7 U4.12@5803.7,5569.2 ; v1(5710,5310) 5725,5295 v1(5725,5190) ; U4.12 U4.12@5803.7,5569.2 ; U2.2 5940,6750 5940,5530 5902.9,5492.9 5880,5492.9 U4.12@5803.7,5569.2 ; v1(6020,4930) 6140,4810 v1(6140,4270)
  Bottom Layer w10: v1(5630,5390) v1(5710,5310) ; v1(5725,5190) 5760,5190 v1(6020,4930) ; 6140,4290 v1(6140,4270) 6140,4230 H4.3
PB9: H4.4 U2.1 U4.11 | length 3272.9
  Top Layer w10: U4.11 5675,5341.3 5675,5190 v1(5820,5045) ; v1(5870,5565) 5910,5605 5910,6815 6010,6915 U2.1 ; v1(6205,4575) 6205,4275 v1(6240,4240)
  Bottom Layer w10: U4.11 5870,5536.3 v1(5870,5565) ; v1(5820,5045) 6205,4660 v1(6205,4575) ; v1@6240,4245 6385,4100 H4.4
VCC: DC1.1 H2.1 H2.2 SW1.2 | length 1424.3
  Top Layer w40: DC1.1@4159.9,7332.4 4162.5,7335 4635,7335 H2.1@4684,7384 ; H2.2 H2.1 4785,7485 5325,7485 5385,7425 SW1.2@5440,7425
pads on no net: SW1.3 u6.ADC u6.INT u6.XCL u6.XDA U12.1 U12.2

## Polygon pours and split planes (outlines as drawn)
GND on Top Layer (solid, remove dead copper, pour order 2): 3370,8225 3370,3040 7520,3040 7520,8225
GND on Bottom Layer (solid, remove dead copper, pour order 2): 3000,8485 3000,3000 7760,3000 7760,8485

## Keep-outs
Board Outline Layer:
  region: 4416.9,3970 4416.5,3962.8 4415.4,3955.6 4413.4,3948.6 4410.7,3941.9 4407.3,3935.5 4403.3,3929.5 4398.6,3924 4393.3,3919 4387.6,3914.6 4381.4,3910.9 4374.8,3907.8 4367.9,3905.5 4360.8,3904 4353.6,3903.2 4346.4,3903.2 4339.2,3904 4332.1,3905.5 4325.2,3907.8 4318.6,3910.9 4312.4,3914.6 4306.7,3919 4301.4,3924 4296.7,3929.5 4292.7,3935.5 4289.3,3941.9 4286.6,3948.6 4284.6,3955.6 4283.5,3962.8 4283.1,3970 4283.5,3977.2 4284.6,3984.4 4286.6,3991.4 4289.3,3998.1 4292.7,4004.5 4296.7,4010.5 4301.4,4016 4306.7,4021 4312.4,4025.4 4318.6,4029.1 4325.2,4032.2 4332.1,4034.5 4339.2,4036 4346.4,4036.8 4353.6,4036.8 4360.8,4036 4367.9,4034.5 4374.8,4032.2 4381.4,4029.1 4387.6,4025.4 4393.3,4021 4398.6,4016 4403.3,4010.5 4407.3,4004.5 4410.7,3998.1 4413.4,3991.4 4415.4,3984.4 4416.5,3977.2
  region: 4416.9,3970 4416.5,3962.8 4415.4,3955.6 4413.4,3948.6 4410.7,3941.9 4407.3,3935.5 4403.3,3929.5 4398.6,3924 4393.3,3919 4387.6,3914.6 4381.4,3910.9 4374.8,3907.8 4367.9,3905.5 4360.8,3904 4353.6,3903.2 4346.4,3903.2 4339.2,3904 4332.1,3905.5 4325.2,3907.8 4318.6,3910.9 4312.4,3914.6 4306.7,3919 4301.4,3924 4296.7,3929.5 4292.7,3935.5 4289.3,3941.9 4286.6,3948.6 4284.6,3955.6 4283.5,3962.8 4283.1,3970 4283.5,3977.2 4284.6,3984.4 4286.6,3991.4 4289.3,3998.1 4292.7,4004.5 4296.7,4010.5 4301.4,4016 4306.7,4021 4312.4,4025.4 4318.6,4029.1 4325.2,4032.2 4332.1,4034.5 4339.2,4036 4346.4,4036.8 4353.6,4036.8 4360.8,4036 4367.9,4034.5 4374.8,4032.2 4381.4,4029.1 4387.6,4025.4 4393.3,4021 4398.6,4016 4403.3,4010.5 4407.3,4004.5 4410.7,3998.1 4413.4,3991.4 4415.4,3984.4 4416.5,3977.2
  region: 6501.9,3970 6501.5,3962.8 6500.4,3955.6 6498.4,3948.6 6495.7,3941.9 6492.3,3935.5 6488.3,3929.5 6483.6,3924 6478.3,3919 6472.6,3914.6 6466.4,3910.9 6459.8,3907.8 6452.9,3905.5 6445.8,3904 6438.6,3903.2 6431.4,3903.2 6424.2,3904 6417.1,3905.5 6410.2,3907.8 6403.6,3910.9 6397.4,3914.6 6391.7,3919 6386.4,3924 6381.7,3929.5 6377.7,3935.5 6374.3,3941.9 6371.6,3948.6 6369.6,3955.6 6368.5,3962.8 6368.1,3970 6368.5,3977.2 6369.6,3984.4 6371.6,3991.4 6374.3,3998.1 6377.7,4004.5 6381.7,4010.5 6386.4,4016 6391.7,4021 6397.4,4025.4 6403.6,4029.1 6410.2,4032.2 6417.1,4034.5 6424.2,4036 6431.4,4036.8 6438.6,4036.8 6445.8,4036 6452.9,4034.5 6459.8,4032.2 6466.4,4029.1 6472.6,4025.4 6478.3,4021 6483.6,4016 6488.3,4010.5 6492.3,4004.5 6495.7,3998.1 6498.4,3991.4 6500.4,3984.4 6501.5,3977.2
  region: 6501.9,3970 6501.5,3962.8 6500.4,3955.6 6498.4,3948.6 6495.7,3941.9 6492.3,3935.5 6488.3,3929.5 6483.6,3924 6478.3,3919 6472.6,3914.6 6466.4,3910.9 6459.8,3907.8 6452.9,3905.5 6445.8,3904 6438.6,3903.2 6431.4,3903.2 6424.2,3904 6417.1,3905.5 6410.2,3907.8 6403.6,3910.9 6397.4,3914.6 6391.7,3919 6386.4,3924 6381.7,3929.5 6377.7,3935.5 6374.3,3941.9 6371.6,3948.6 6369.6,3955.6 6368.5,3962.8 6368.1,3970 6368.5,3977.2 6369.6,3984.4 6371.6,3991.4 6374.3,3998.1 6377.7,4004.5 6381.7,4010.5 6386.4,4016 6391.7,4021 6397.4,4025.4 6403.6,4029.1 6410.2,4032.2 6417.1,4034.5 6424.2,4036 6431.4,4036.8 6438.6,4036.8 6445.8,4036 6452.9,4034.5 6459.8,4032.2 6466.4,4029.1 6472.6,4025.4 6478.3,4021 6483.6,4016 6488.3,4010.5 6492.3,4004.5 6495.7,3998.1 6498.4,3991.4 6500.4,3984.4 6501.5,3977.2
  region: 4416.9,7460 4416.5,7452.8 4415.4,7445.6 4413.4,7438.6 4410.7,7431.9 4407.3,7425.5 4403.3,7419.5 4398.6,7414 4393.3,7409 4387.6,7404.6 4381.4,7400.9 4374.8,7397.8 4367.9,7395.5 4360.8,7394 4353.6,7393.2 4346.4,7393.2 4339.2,7394 4332.1,7395.5 4325.2,7397.8 4318.6,7400.9 4312.4,7404.6 4306.7,7409 4301.4,7414 4296.7,7419.5 4292.7,7425.5 4289.3,7431.9 4286.6,7438.6 4284.6,7445.6 4283.5,7452.8 4283.1,7460 4283.5,7467.2 4284.6,7474.4 4286.6,7481.4 4289.3,7488.1 4292.7,7494.5 4296.7,7500.5 4301.4,7506 4306.7,7511 4312.4,7515.4 4318.6,7519.1 4325.2,7522.2 4332.1,7524.5 4339.2,7526 4346.4,7526.8 4353.6,7526.8 4360.8,7526 4367.9,7524.5 4374.8,7522.2 4381.4,7519.1 4387.6,7515.4 4393.3,7511 4398.6,7506 4403.3,7500.5 4407.3,7494.5 4410.7,7488.1 4413.4,7481.4 4415.4,7474.4 4416.5,7467.2
  region: 4416.9,7460 4416.5,7452.8 4415.4,7445.6 4413.4,7438.6 4410.7,7431.9 4407.3,7425.5 4403.3,7419.5 4398.6,7414 4393.3,7409 4387.6,7404.6 4381.4,7400.9 4374.8,7397.8 4367.9,7395.5 4360.8,7394 4353.6,7393.2 4346.4,7393.2 4339.2,7394 4332.1,7395.5 4325.2,7397.8 4318.6,7400.9 4312.4,7404.6 4306.7,7409 4301.4,7414 4296.7,7419.5 4292.7,7425.5 4289.3,7431.9 4286.6,7438.6 4284.6,7445.6 4283.5,7452.8 4283.1,7460 4283.5,7467.2 4284.6,7474.4 4286.6,7481.4 4289.3,7488.1 4292.7,7494.5 4296.7,7500.5 4301.4,7506 4306.7,7511 4312.4,7515.4 4318.6,7519.1 4325.2,7522.2 4332.1,7524.5 4339.2,7526 4346.4,7526.8 4353.6,7526.8 4360.8,7526 4367.9,7524.5 4374.8,7522.2 4381.4,7519.1 4387.6,7515.4 4393.3,7511 4398.6,7506 4403.3,7500.5 4407.3,7494.5 4410.7,7488.1 4413.4,7481.4 4415.4,7474.4 4416.5,7467.2
  region: 6501.9,7455 6501.5,7447.8 6500.4,7440.6 6498.4,7433.6 6495.7,7426.9 6492.3,7420.5 6488.3,7414.5 6483.6,7409 6478.3,7404 6472.6,7399.6 6466.4,7395.9 6459.8,7392.8 6452.9,7390.5 6445.8,7389 6438.6,7388.2 6431.4,7388.2 6424.2,7389 6417.1,7390.5 6410.2,7392.8 6403.6,7395.9 6397.4,7399.6 6391.7,7404 6386.4,7409 6381.7,7414.5 6377.7,7420.5 6374.3,7426.9 6371.6,7433.6 6369.6,7440.6 6368.5,7447.8 6368.1,7455 6368.5,7462.2 6369.6,7469.4 6371.6,7476.4 6374.3,7483.1 6377.7,7489.5 6381.7,7495.5 6386.4,7501 6391.7,7506 6397.4,7510.4 6403.6,7514.1 6410.2,7517.2 6417.1,7519.5 6424.2,7521 6431.4,7521.8 6438.6,7521.8 6445.8,7521 6452.9,7519.5 6459.8,7517.2 6466.4,7514.1 6472.6,7510.4 6478.3,7506 6483.6,7501 6488.3,7495.5 6492.3,7489.5 6495.7,7483.1 6498.4,7476.4 6500.4,7469.4 6501.5,7462.2
  region: 6501.9,7455 6501.5,7447.8 6500.4,7440.6 6498.4,7433.6 6495.7,7426.9 6492.3,7420.5 6488.3,7414.5 6483.6,7409 6478.3,7404 6472.6,7399.6 6466.4,7395.9 6459.8,7392.8 6452.9,7390.5 6445.8,7389 6438.6,7388.2 6431.4,7388.2 6424.2,7389 6417.1,7390.5 6410.2,7392.8 6403.6,7395.9 6397.4,7399.6 6391.7,7404 6386.4,7409 6381.7,7414.5 6377.7,7420.5 6374.3,7426.9 6371.6,7433.6 6369.6,7440.6 6368.5,7447.8 6368.1,7455 6368.5,7462.2 6369.6,7469.4 6371.6,7476.4 6374.3,7483.1 6377.7,7489.5 6381.7,7495.5 6386.4,7501 6391.7,7506 6397.4,7510.4 6403.6,7514.1 6410.2,7517.2 6417.1,7519.5 6424.2,7521 6431.4,7521.8 6438.6,7521.8 6445.8,7521 6452.9,7519.5 6459.8,7517.2 6466.4,7514.1 6472.6,7510.4 6478.3,7506 6483.6,7501 6488.3,7495.5 6492.3,7489.5 6495.7,7483.1 6498.4,7476.4 6500.4,7469.4 6501.5,7462.2
  lines w0.1: 4283.1,3970 4283.5,3962.8 4284.6,3955.6 4286.6,3948.6 4289.3,3941.9 4292.7,3935.5 4296.7,3929.5 4301.4,3924 4306.7,3919 4312.4,3914.6 4318.6,3910.9 4325.2,3907.8 4332.1,3905.5 4339.2,3904 4346.4,3903.2 4353.6,3903.2 4360.8,3904 4367.9,3905.5 4374.8,3907.8 4381.4,3910.9 4387.6,3914.6 4393.3,3919 4398.6,3924 4403.3,3929.5 4407.3,3935.5 4410.7,3941.9 4413.4,3948.6 4415.4,3955.6 4416.5,3962.8 4416.9,3970 4416.5,3977.2 4415.4,3984.4 4413.4,3991.4 4410.7,3998.1 4407.3,4004.5 4403.3,4010.5 4398.6,4016 4393.3,4021 4387.6,4025.4 4381.4,4029.1 4374.8,4032.2 4367.9,4034.5 4360.8,4036 4353.6,4036.8 4346.4,4036.8 4339.2,4036 4332.1,4034.5 4325.2,4032.2 4318.6,4029.1 4312.4,4025.4 4306.7,4021 4301.4,4016 4296.7,4010.5 4292.7,4004.5 4289.3,3998.1 4286.6,3991.4 4284.6,3984.4 4283.5,3977.2 4283.1,3970 ; 4283.1,7460 4283.5,7452.8 4284.6,7445.6 4286.6,7438.6 4289.3,7431.9 4292.7,7425.5 4296.7,7419.5 4301.4,7414 4306.7,7409 4312.4,7404.6 4318.6,7400.9 4325.2,7397.8 4332.1,7395.5 4339.2,7394 4346.4,7393.2 4353.6,7393.2 4360.8,7394 4367.9,7395.5 4374.8,7397.8 4381.4,7400.9 4387.6,7404.6 4393.3,7409 4398.6,7414 4403.3,7419.5 4407.3,7425.5 4410.7,7431.9 4413.4,7438.6 4415.4,7445.6 4416.5,7452.8 4416.9,7460 4416.5,7467.2 4415.4,7474.4 4413.4,7481.4 4410.7,7488.1 4407.3,7494.5 4403.3,7500.5 4398.6,7506 4393.3,7511 4387.6,7515.4 4381.4,7519.1 4374.8,7522.2 4367.9,7524.5 4360.8,7526 4353.6,7526.8 4346.4,7526.8 4339.2,7526 4332.1,7524.5 4325.2,7522.2 4318.6,7519.1 4312.4,7515.4 4306.7,7511 4301.4,7506 4296.7,7500.5 4292.7,7494.5 4289.3,7488.1 4286.6,7481.4 4284.6,7474.4 4283.5,7467.2 4283.1,7460 ; 6368.1,3970 6368.5,3962.8 6369.6,3955.6 6371.6,3948.6 6374.3,3941.9 6377.7,3935.5 6381.7,3929.5 6386.4,3924 6391.7,3919 6397.4,3914.6 6403.6,3910.9 6410.2,3907.8 6417.1,3905.5 6424.2,3904 6431.4,3903.2 6438.6,3903.2 6445.8,3904 6452.9,3905.5 6459.8,3907.8 6466.4,3910.9 6472.6,3914.6 6478.3,3919 6483.6,3924 6488.3,3929.5 6492.3,3935.5 6495.7,3941.9 6498.4,3948.6 6500.4,3955.6 6501.5,3962.8 6501.9,3970 6501.5,3977.2 6500.4,3984.4 6498.4,3991.4 6495.7,3998.1 6492.3,4004.5 6488.3,4010.5 6483.6,4016 6478.3,4021 6472.6,4025.4 6466.4,4029.1 6459.8,4032.2 6452.9,4034.5 6445.8,4036 6438.6,4036.8 6431.4,4036.8 6424.2,4036 6417.1,4034.5 6410.2,4032.2 6403.6,4029.1 6397.4,4025.4 6391.7,4021 6386.4,4016 6381.7,4010.5 6377.7,4004.5 6374.3,3998.1 6371.6,3991.4 6369.6,3984.4 6368.5,3977.2 6368.1,3970 ; 6368.1,7455 6368.5,7447.8 6369.6,7440.6 6371.6,7433.6 6374.3,7426.9 6377.7,7420.5 6381.7,7414.5 6386.4,7409 6391.7,7404 6397.4,7399.6 6403.6,7395.9 6410.2,7392.8 6417.1,7390.5 6424.2,7389 6431.4,7388.2 6438.6,7388.2 6445.8,7389 6452.9,7390.5 6459.8,7392.8 6466.4,7395.9 6472.6,7399.6 6478.3,7404 6483.6,7409 6488.3,7414.5 6492.3,7420.5 6495.7,7426.9 6498.4,7433.6 6500.4,7440.6 6501.5,7447.8 6501.9,7455 6501.5,7462.2 6500.4,7469.4 6498.4,7476.4 6495.7,7483.1 6492.3,7489.5 6488.3,7495.5 6483.6,7501 6478.3,7506 6472.6,7510.4 6466.4,7514.1 6459.8,7517.2 6452.9,7519.5 6445.8,7521 6438.6,7521.8 6431.4,7521.8 6424.2,7521 6417.1,7519.5 6410.2,7517.2 6403.6,7514.1 6397.4,7510.4 6391.7,7506 6386.4,7501 6381.7,7495.5 6377.7,7489.5 6374.3,7483.1 6371.6,7476.4 6369.6,7469.4 6368.5,7462.2 6368.1,7455
  lines w10: 4015,3840 4015,7550 6825,7550 6825,3840 4015,3840

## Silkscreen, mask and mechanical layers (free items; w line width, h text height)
Top Silkscreen Layer:
  text "2025电赛校赛专用" at 6275,6630 h120 r270
Mechanical Layer:
  drawing of 232 lines, arcs and shapes, not listed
